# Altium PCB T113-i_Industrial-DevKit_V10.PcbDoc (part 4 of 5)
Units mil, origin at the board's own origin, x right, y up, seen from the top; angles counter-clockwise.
Board outline 4212.61 x 3188.98 mil, 4 copper layers (Top Layer, GND, PWR, Bottom Layer); 249 components, 236 nets, 911 pads, 571 vias.
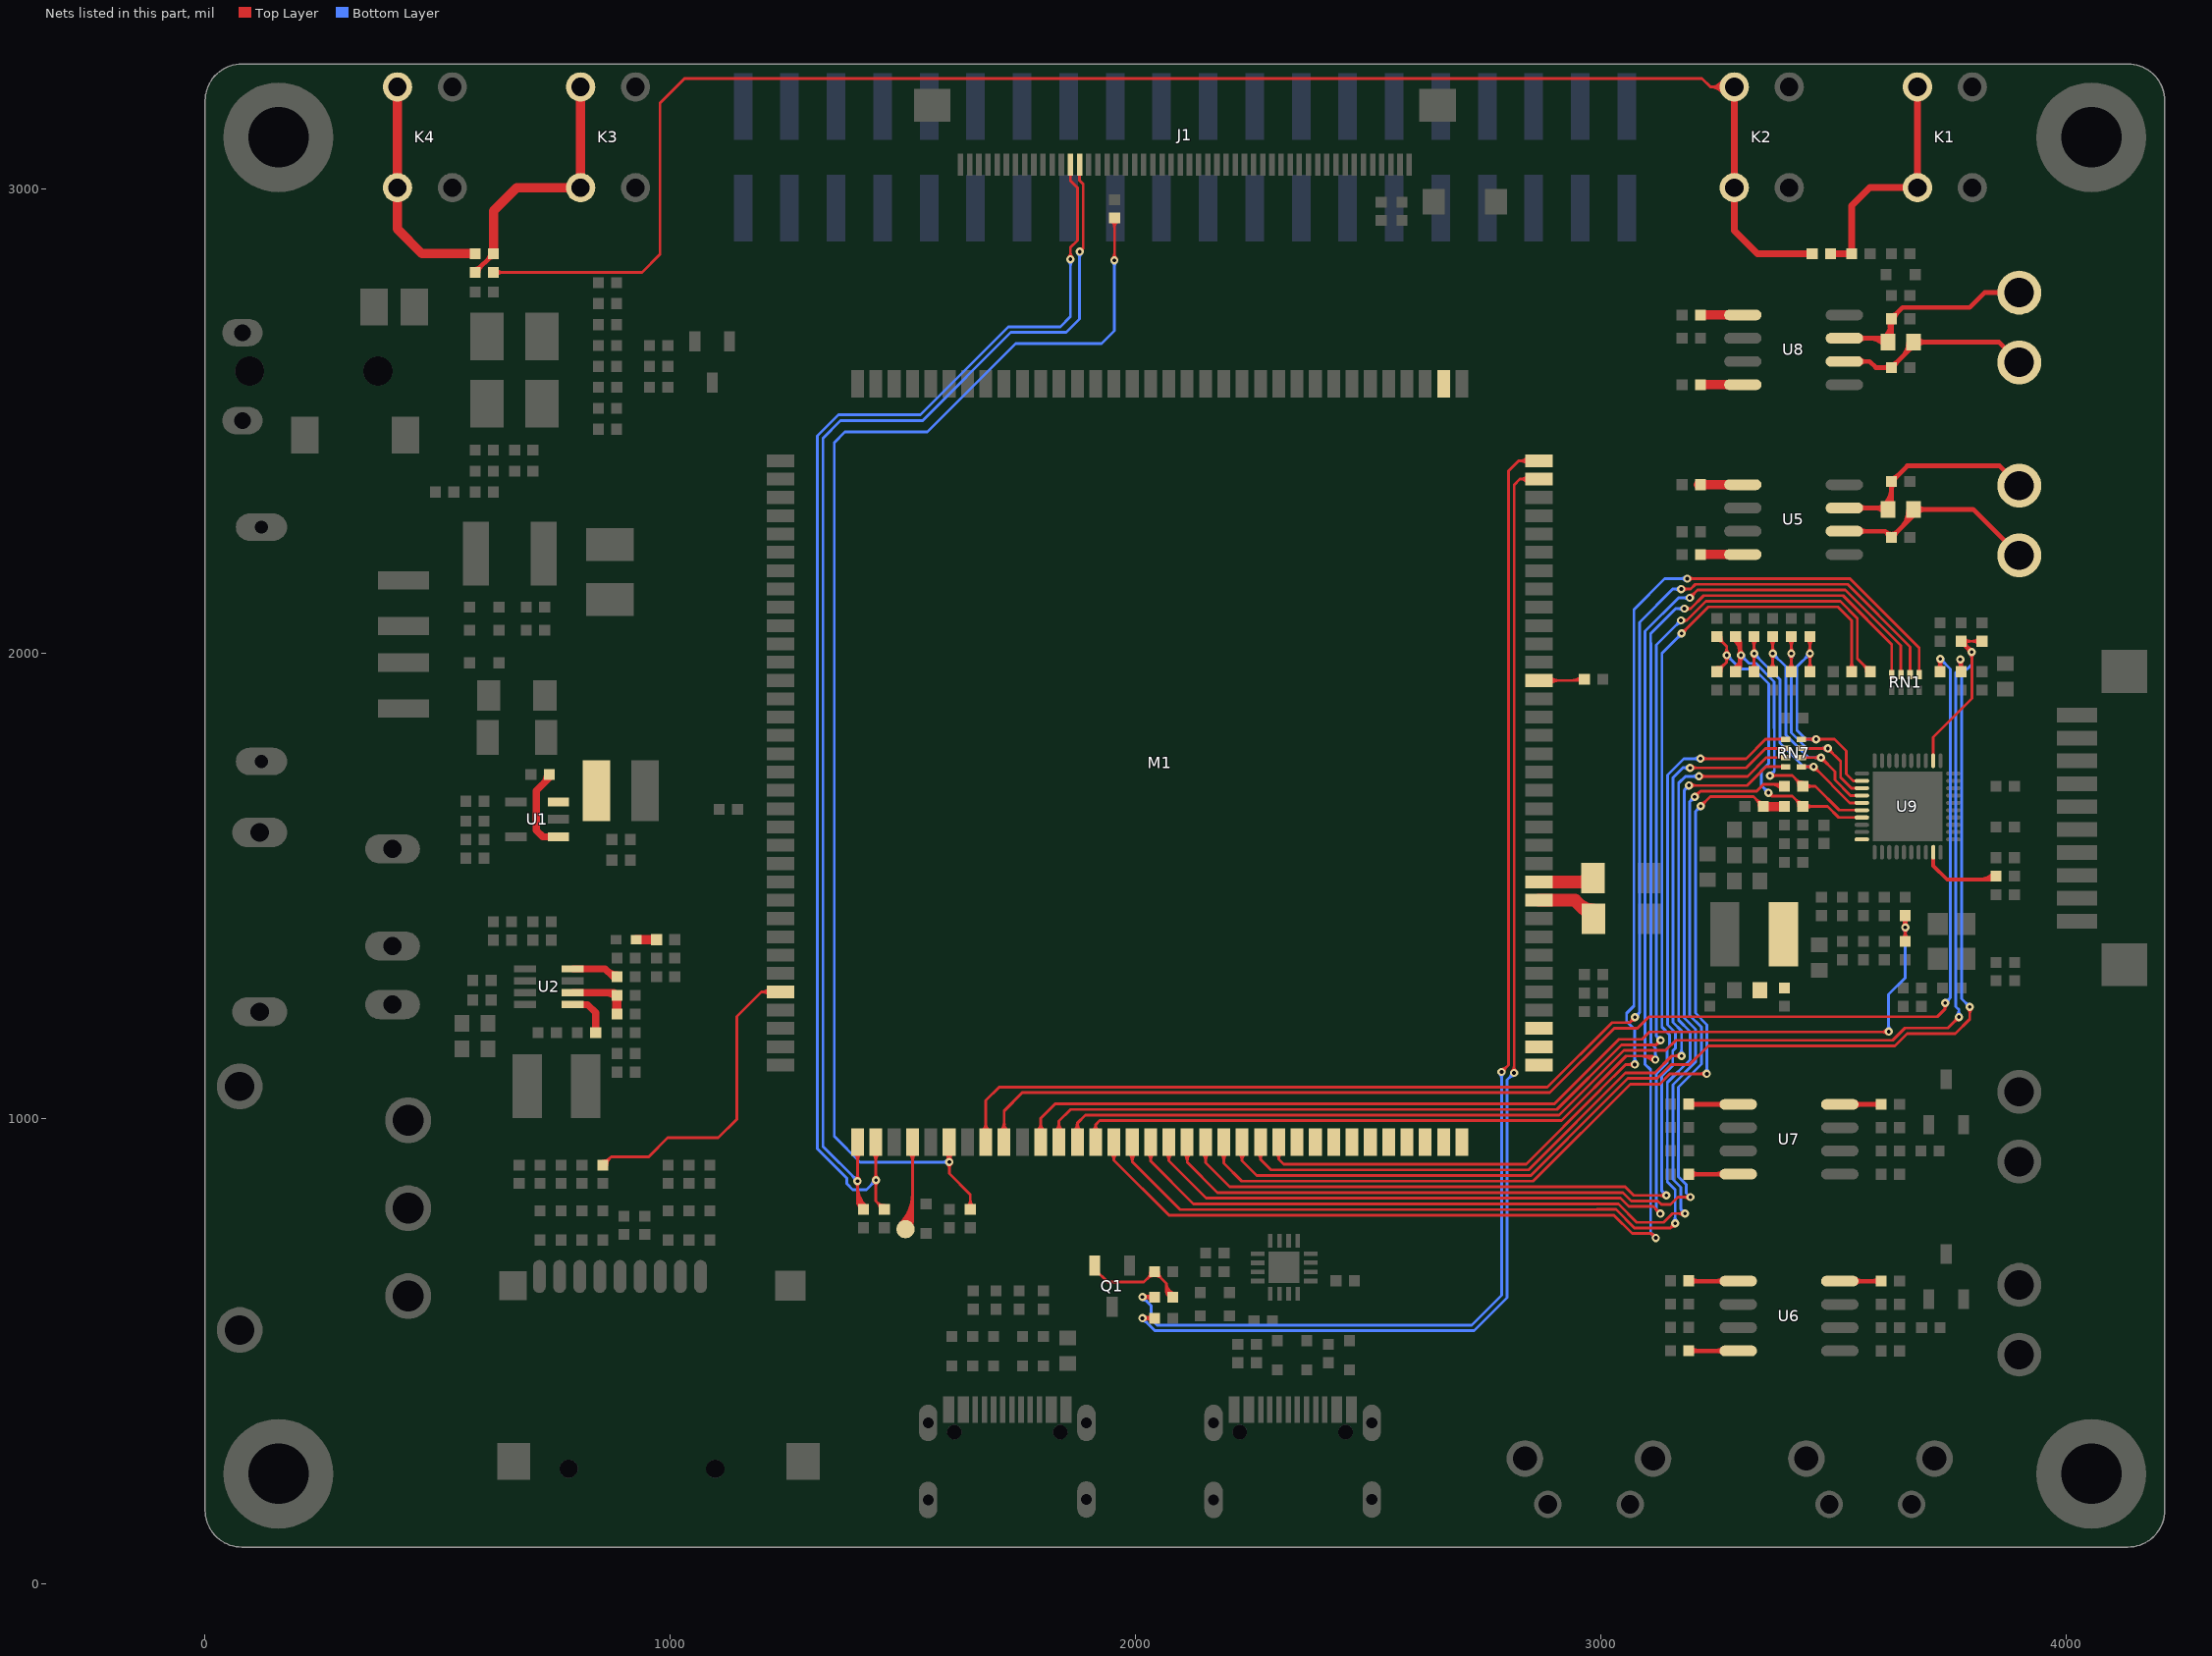
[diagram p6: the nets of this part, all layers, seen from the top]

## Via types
v1: diameter 17.72, hole 7.87, Top Layer to Bottom Layer, tented both sides, 571 vias

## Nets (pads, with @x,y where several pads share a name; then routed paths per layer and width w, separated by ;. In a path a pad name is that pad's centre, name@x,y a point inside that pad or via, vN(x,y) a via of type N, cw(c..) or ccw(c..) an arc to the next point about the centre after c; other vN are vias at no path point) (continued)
NetJ6_1: J6.1 R51.2 R52.1 U5.6 | length 634.6
  Top Layer w10: U5.6@3524.15,2263.15 3612.17,2263.15 R51.2@3625.31,2250 3672.56,2297.24 R52.1@3672.56,2310 3801.25,2310 J6.1@3900,2211.25 ; U5.6@3557.48,2258.5 cw(c3568.71,2247.28) 3568.71,2263.15 cw(c3568.71,2279.02) U5.6@3557.48,2267.8 ; R51.2@3618.5,2250 ccw(c3602.06,2250) 3613.69,2261.63 ccw(c3625.31,2273.25) 3625.31,2256.81 ccw(c3625.31,2273.25) 3636.94,2261.63 ccw(c3648.57,2250) R51.2@3632.13,2250 ; 3646.58,2271.27 ccw(c3609.82,2308.03) R52.1@3661.81,2308.03 ; 3663.65,2288.34 ccw(c3643.96,2308.03) R52.1@3671.81,2308.03 ; R52.1@3680.16,2302.4 cw(c3698.51,2284.05) 3698.51,2310 cw(c3698.51,2335.95) R52.1@3680.16,2317.6
NetJ6_2: J6.2 R52.2 R53.1 U5.7 | length 645.5
  Top Layer w10: U5.7@3524.15,2313.15 3614.29,2313.15 R52.2@3617.44,2310 3625.32,2317.87 R53.1@3625.32,2370 3659.12,2403.8 3857.45,2403.8 J6.2@3900,2361.26 ; U5.7@3557.48,2308.5 cw(c3568.71,2297.28) 3568.71,2313.15 cw(c3568.71,2329.02) U5.7@3557.48,2317.8 ; 3588.64,2313.15 cw(c3588.64,2283.17) R52.2@3609.84,2304.37 ; 3594.34,2313.15 ccw(c3594.34,2335.06) 3609.84,2319.57 ccw(c3572.48,2356.93) 3625.32,2356.93 ; R52.2@3616.91,2312.5 ccw(c3596.63,2332.78) 3625.32,2332.78 ; R53.1@3620.5,2365.18 cw(c3608.87,2353.56) 3625.32,2353.56 cw(c3641.76,2353.56) R53.1@3630.13,2365.18 ; R53.1@3625.32,2376.81 ccw(c3625.32,2393.25) 3636.94,2381.63 ccw(c3648.57,2370) R53.1@3632.13,2370
NetJ9_1: J9.1 R60.2 R61.1 U8.6 | length 584.8
  Top Layer w10: U8.6@3524.15,2628.15 3578.5,2628.15 3591.65,2615 R60.2@3625.31,2615 3672.56,2662.24 R61.1@3672.56,2670 3856.25,2670 J9.1@3900,2626.25 ; U8.6@3557.48,2623.5 cw(c3568.71,2612.28) 3568.71,2628.15 cw(c3568.71,2644.02) U8.6@3557.48,2632.8 ; R60.2@3620.5,2610.18 ccw(c3608.87,2598.56) 3608.87,2615 ccw(c3608.87,2631.44) R60.2@3620.5,2619.82 ; R60.2@3625.31,2621.81 ccw(c3625.31,2638.25) 3636.94,2626.63 ccw(c3648.57,2615) R60.2@3632.13,2615 ; 3650.12,2639.8 ccw(c3621.89,2668.03) R61.1@3661.81,2668.03 ; R61.1@3664.09,2653.78 cw(c3672.56,2645.31) R61.1@3672.56,2657.28 ; R61.1@3680.16,2662.4 cw(c3698.51,2644.05) 3698.51,2670 cw(c3698.51,2695.95) R61.1@3680.16,2677.6
NetJ9_2: J9.2 R61.2 R62.1 U8.7 | length 669.3
  Top Layer w10: U8.7@3524.15,2678.15 3609.29,2678.15 R61.2@3617.44,2670 3625.32,2677.87 R62.1@3625.32,2720 3649.45,2744.14 3793.19,2744.14 3825.31,2776.26 J9.2@3900,2776.26 ; U8.7@3557.48,2673.5 cw(c3568.71,2662.28) 3568.71,2678.15 cw(c3568.71,2694.02) U8.7@3557.48,2682.8 ; 3576.57,2678.15 cw(c3576.57,2631.1) R61.2@3609.84,2664.37 ; 3600.71,2678.15 cw(c3600.71,2655.24) R61.2@3616.91,2671.44 ; R61.2@3609.84,2679.57 ccw(c3572.48,2716.93) R62.1@3625.32,2716.93 ; R61.2@3616.91,2672.5 ccw(c3596.63,2692.78) 3625.32,2692.78 ; R62.1@3619.42,2716.59 cw(c3602.82,2707.01) 3621.33,2702.06 ; R62.1@3620.5,2715.18 cw(c3608.87,2703.56) 3625.32,2703.56 cw(c3641.76,2703.56) R62.1@3630.13,2715.18 ; 3622.32,2705.77 cw(c3635.58,2702.21) R62.1@3628.72,2714.1 ; R62.1@3625.32,2726.81 ccw(c3625.32,2743.25) 3636.94,2731.63 ccw(c3648.57,2720) R62.1@3632.13,2720
NetK1_1: K1.1 K1.2 R14.1 R16.2 | length 522.4
  Top Layer w15: R16.2@3494.37,2860 R14.1@3540,2860 3540,2963 3578.96,3001.96 K1.1@3681.1,3001.96 K1.2@3681.1,3218.51
NetK2_1: K2.1 K2.2 R16.1 R19.2 | length 3684.1
  Top Layer w6: R19.2@619.69,2820 939.38,2820 977.79,2858.41 977.79,3183.72 1030.71,3236.64 3218.09,3236.64 3236.23,3218.51 ; R19.2@625.92,2813.77 cw(c640.96,2798.73) 640.96,2820 cw(c640.96,2841.27) R19.2@625.92,2826.23 ; K2.2@3263.18,3203.5 ccw(c3236.23,3186.81) 3236.23,3218.51 ; K2.2@3263.18,3233.52 cw(c3236.23,3250.21) 3236.23,3218.51 ; K2.2@3268.28,3206.66 ccw(c3247,3193.48) 3247,3218.51 ccw(c3247,3243.54) K2.2@3268.28,3230.36 ; K2.2@3287.4,3218.51 3236.23,3218.51
  Top Layer w15: K2.2@3287.4,3218.51 K2.1@3287.4,3001.96 3287.4,2909.6 3337,2860 R16.1@3455,2860
NetK3_1: K3.1 K3.2 R19.1 R23.2 | length 624.4
  Top Layer w10: R19.1@580.32,2820 619.69,2859.37 R23.2@619.69,2860 ; R19.1@580.32,2826.81 ccw(c580.32,2843.25) 591.94,2831.63 ccw(c603.57,2820) R19.1@587.13,2820 ; 607.61,2847.3 ccw(c594.91,2860) R23.2@612.87,2860 ; R23.2@609.13,2848.82 cw(c619.69,2838.27) R23.2@619.69,2853.19
  Top Layer w20: R23.2@619.69,2860 619.69,2951.69 669.96,3001.96 K3.1@807.09,3001.96 K3.2@807.09,3218.51
NetK4_1: K4.1 K4.2 R23.1 | length 494.6
  Top Layer w20: K4.2@413.39,3218.51 K4.1@413.39,3001.96 413.39,2912.67 466.05,2860 R23.1@580.32,2860
NetL1_1: L1.1 U1.3
NetLED1_1: LED1.1 R12.1 | length 43.7
  Top Layer w20: LED1.1@926.65,1385 R12.1@970.32,1385
NetM1_38: M1.38 TP1.1 | length 495.2
  Top Layer w6: TP1.1@1493.8,774.17 ccw(c1428.93,839.04) 1520.67,839.04 ; TP1.1@1498.04,769.93 ccw(c1443.42,824.55) 1520.67,824.55 ; TP1.1@1502.29,765.69 ccw(c1457.9,810.07) 1520.67,810.07 ; TP1.1@1505.6,762.37 1520.67,777.44 ; TP1.1@1506.53,761.44 ccw(c1472.39,795.58) 1520.67,795.58 ; TP1.1@1510.77,757.2 ccw(c1486.87,781.1) 1520.67,781.1 ; M1.38@1513.05,926.63 cw(c1494.64,908.23) 1520.67,908.23 cw(c1546.69,908.23) M1.38@1528.29,926.63 ; TP1.1@1514.22,776.66 ccw(c1516.94,781.17) 1520.67,777.44 ; TP1.1@1519.88,771 cw(c1524.39,773.72) 1520.67,777.44 ; M1.38@1520.67,950 1520.67,777.44
NetM1_78: M1.78 R65.1 | length 169.1
  Top Layer w28: M1.78@2867.13,1469.69 2945.08,1469.69 R65.1@2984.76,1430 ; 2953.22,1461.55 ccw(c2984.76,1493.1) R65.1@2984.76,1448.48
NetM1_79: M1.79 R66.1 | length 142.6
  Top Layer w28: M1.79@2867.13,1509.06 2975.64,1509.06 R66.1@2983.77,1517.19 ; 2955.65,1509.06 ccw(c2955.65,1537.83) R66.1@2975.99,1517.48
NetM1_90: M1.90 R67.2 | length 186.7
  Top Layer w6: M1.90@2867.13,1942.13 2962.44,1942.13 R67.2@2965.31,1945 ; M1.90@2890.5,1934.5 cw(c2908.9,1916.1) 2908.9,1942.13 cw(c2908.9,1968.15) M1.90@2890.5,1949.75 ; 2937.11,1942.13 ccw(c2937.11,1973.21) R67.2@2959.08,1951.23 ; 2950.98,1942.13 cw(c2950.98,1930.67) R67.2@2959.08,1938.77 ; 2951.59,1942.13 ccw(c2951.59,1958.72) R67.2@2963.33,1946.99
NetQ1_2: Q1.2 R35.2 R37.2 | length 401.9
  Top Layer w6: Q1.2@1912.6,684.29 1912.6,676.1 1940.28,648.41 2018.18,648.41 R37.2@2040.98,671.22 2066.53,645.68 ; R37.2@2032.17,671.22 cw(c2010.9,671.22) 2025.94,656.18 cw(c2040.98,641.14) 2040.98,662.41 cw(c2040.98,641.14) 2056.03,656.18 cw(c2071.07,671.22) R37.2@2049.8,671.22 ; 2066.53,637.87 ccw(c2086.12,637.87) R35.2@2081.08,618.94 ; R35.2@2071.56,616.76 ccw(c2054.3,617.82) 2066.53,630.05 ; R35.2@2079.53,613.14 cw(c2084.04,630.06) 2066.53,630.06 ; R35.2@2079.81,625.01 cw(c2078.76,642.28) 2066.53,630.05 ; R35.2@2080.35,616.22 2066.53,630.05 ; R35.2@2082.62,624.73 cw(c2088.2,645.68) 2066.53,645.68 ; 2066.53,630.05 2066.53,645.68
NetR1_1: R1.1 U1.1 | length 206.4
  Top Layer w15: 727.09,1720 ccw(c707.08,1740) R1.1@735.37,1740 ; R1.1@739.68,1740 739.68,1732.59 712,1704.91 712,1620 725.65,1606.35 U1.1@759.08,1606.35
NetR4_1: R4.1 R7.2 U2.6 | length 161.6
  Top Layer w15: U2.6@790.26,1270.92 879.39,1270.92 R4.1@885.32,1265 ; 860.61,1270.92 cw(c860.61,1240.3) R4.1@882.27,1261.95
  Top Layer w20: R7.2@885.31,1225 R4.1@885.32,1265
NetR8_2: R8.2 U2.8 | length 126.3
  Top Layer w15: U2.8@790.26,1322.1 859.8,1322.1 876.91,1305 R8.2@885.31,1305 ; 863.6,1318.3 ccw(c885.31,1340.02) R8.2@885.31,1309.31
NetR9_2: R9.2 U2.5 | length 99.5
  Top Layer w15: U2.5@790.26,1245.33 822.21,1245.33 839.69,1227.85 R9.2@839.69,1185
NetR43_2: R43.2 U5.4 | length 91.2
  Top Layer w20: R43.2@3214.69,2213.15 U5.4@3305.85,2213.15
NetR44_2: R44.2 U5.1 | length 95.6
  Top Layer w20: R44.2@3210.24,2363.15 U5.1@3305.85,2363.15
NetR45_1: R45.1 U6.4 | length 157.2
  Top Layer w10: R45.1@3189.68,501.26 3190.31,500.63 U6.4@3295.85,500.63 ; R45.1@3194.5,496.44 cw(c3204.61,486.34) 3204.61,500.63 ; R45.1@3194.5,506.08 ccw(c3207.65,519.22) 3207.65,500.63 ; U6.4@3262.52,495.98 ccw(c3251.29,484.76) 3251.29,500.63 ccw(c3251.29,516.5) U6.4@3262.52,505.28
NetR46_1: R46.1 U6.1 | length 157.2
  Top Layer w10: R46.1@3189.68,651.26 3190.31,650.63 U6.1@3295.85,650.63 ; R46.1@3194.5,646.44 cw(c3204.61,636.34) 3204.61,650.63 ; R46.1@3194.5,656.08 ccw(c3207.65,669.22) 3207.65,650.63 ; U6.1@3262.52,645.98 ccw(c3251.29,634.76) 3251.29,650.63 ccw(c3251.29,666.5) U6.1@3262.52,655.28
NetR47_1: R47.1 U7.4 | length 156.9
  Top Layer w10: R47.1@3189.68,880.63 U7.4@3295.85,880.63 ; R47.1@3194.5,875.81 cw(c3206.13,864.19) 3206.13,880.63 cw(c3206.13,897.07) R47.1@3194.5,885.45 ; U7.4@3262.52,875.98 ccw(c3251.29,864.76) 3251.29,880.63 ccw(c3251.29,896.5) U7.4@3262.52,885.28
NetR48_1: R48.1 U7.1 | length 157.2
  Top Layer w10: R48.1@3189.68,1031.26 3190.31,1030.63 U7.1@3295.85,1030.63 ; R48.1@3194.5,1026.44 cw(c3204.61,1016.34) 3204.61,1030.63 ; R48.1@3194.5,1036.08 ccw(c3207.65,1049.22) 3207.65,1030.63 ; U7.1@3262.52,1025.98 ccw(c3251.29,1014.76) 3251.29,1030.63 ccw(c3251.29,1046.5) U7.1@3262.52,1035.28
NetR49_2: R49.2 U6.8 | length 140
  Top Layer w10: U6.8@3514.15,650.63 R49.2@3603.39,650.63 ; U6.8@3547.48,645.98 cw(c3558.71,634.76) 3558.71,650.63 cw(c3558.71,666.5) U6.8@3547.48,655.28 ; R49.2@3598.57,645.81 ccw(c3586.94,634.19) 3586.94,650.63 ccw(c3586.94,667.07) R49.2@3598.57,655.45
NetR50_2: R50.2 U7.8 | length 140
  Top Layer w10: U7.8@3514.15,1030.63 R50.2@3603.39,1030.63 ; U7.8@3547.48,1025.98 cw(c3558.71,1014.76) 3558.71,1030.63 cw(c3558.71,1046.5) U7.8@3547.48,1035.28 ; R50.2@3598.57,1025.81 ccw(c3586.94,1014.19) 3586.94,1030.63 ccw(c3586.94,1047.07) R50.2@3598.57,1035.45
NetR58_2: R58.2 U8.4 | length 90.6
  Top Layer w20: R58.2@3215.24,2578.15 U8.4@3305.85,2578.15
NetR59_2: R59.2 U8.1 | length 90.6
  Top Layer w20: R59.2@3215.24,2728.15 U8.1@3305.85,2728.15
PB8: M1.101 R36.1 | length 2859
  Top Layer w6: v1(2014.89,570.92) 2040.9,570.92 R36.1@2040.98,571 ; v1@2018.66,575.4 ccw(c2025.53,583.59) 2028.29,573.27 ; v1@2018.74,566.49 cw(c2025.55,558.66) 2028.23,568.69 ; v1@2019.04,566.77 cw(c2029.04,556.77) 2029.04,570.92 cw(c2029.04,585.06) v1@2019.04,575.06 ; v1@2019.51,570.92 ccw(c2019.51,592.47) R36.1@2034.75,577.23 ; v1@2019.92,570.92 cw(c2019.92,549.93) R36.1@2034.75,564.77 ; v1@2019.97,567.99 cw(c2028.68,562.95) 2026.08,572.68 ; v1@2019.97,573.85 ccw(c2028.37,578.7) 2025.86,569.32 ; v1@2809.71,1102.43 ccw(c2798.89,1113.26) 2814.2,1113.26 ; v1@2814.2,1098.29 2814.2,2362.88 2826.52,2375.2 ; 2814.2,1111.6 ccw(c2827.17,1111.6) v1@2818,1102.43 ; M1.101@2843.51,2367.83 ccw(c2826.52,2351.92) 2826.52,2375.2 ; M1.101@2843.51,2382.57 cw(c2826.52,2398.48) 2826.52,2375.2 ; M1.101@2867.13,2375.2 2826.52,2375.2
  Bottom Layer w6: v1@2014.89,565.06 cw(c2014.89,550.91) 2024.9,560.92 cw(c2034.9,570.92) v1@2020.75,570.92 ; v1(2014.89,570.92) 2041.7,544.11 2728.06,544.11 2799.1,615.15 2799.1,1083.53 v1(2813.86,1098.29) ; v1@2808,1098.29 cw(c2793.86,1098.29) 2803.86,1088.29 cw(c2813.86,1078.29) v1@2813.86,1092.43
PB9: M1.102 R35.1 | length 2918.8
  Top Layer w6: v1(2014.89,616.5) 2040.7,616.5 R35.1@2040.98,616.22 ; v1@2018.57,611.94 cw(c2025.5,603.32) 2028.36,614 ; v1@2018.83,620.84 ccw(c2025.57,628.28) 2028.17,618.59 ; v1@2019.04,612.36 cw(c2029.04,602.36) 2029.04,616.5 cw(c2029.04,630.65) v1@2019.04,620.65 ; v1@2019.03,616.51 cw(c2019.03,594.26) R35.1@2034.75,609.99 ; v1@2019.97,613.58 cw(c2028,608.94) 2025.6,617.9 ; v1@2019.97,619.43 ccw(c2029.05,624.68) 2026.34,614.55 ; v1@2020.4,616.5 ccw(c2020.4,636.8) R35.1@2034.75,622.45 ; v1(2787.05,1100.58) 2801.83,1115.36 2801.83,2392.66 2823.73,2414.57 M1.102@2867.13,2414.57 ; v1@2787.05,1106.44 ccw(c2787.05,1120.58) 2797.05,1110.58 ccw(c2807.05,1100.58) v1@2792.91,1100.58 ; M1.102@2843.76,2406.95 ccw(c2825.35,2388.54) 2825.35,2414.57 ccw(c2825.35,2440.59) M1.102@2843.76,2422.19
  Bottom Layer w6: v1@2014.89,610.65 cw(c2014.89,596.5) 2024.89,606.5 cw(c2034.9,616.5) v1@2020.75,616.5 ; v1(2014.89,616.5) 2033.91,597.49 2033.91,568.87 2046.67,556.11 2723.09,556.11 2787.1,620.12 2787.1,1100.53 v1(2787.05,1100.58) ; v1@2782.91,1096.44 cw(c2772.79,1086.32) 2787.1,1086.32 ; 2787.1,1086.55 cw(c2801.08,1086.55) v1@2791.2,1096.44
PB12: M1.104
PG6: M1.68
PG7: M1.67
PG8: M1.66
PG9: M1.65
PG10: M1.64
PG11: M1.63
PG12: M1.59
PG13: M1.60
PG14: M1.61
PG15: M1.62
PG16: M1.71
PG17: M1.69
PG18: M1.70
PHYRSTB: C70.1 M1.56 R84.1 U9.12 | length 3214.8
  Top Layer w6: M1.56@2221.96,926.39 cw(c2205.99,909.36) 2229.33,909.36 ; M1.56@2229.33,950 2229.33,909.36 ; M1.56@2236.71,926.39 ccw(c2252.67,909.36) 2229.33,909.36 ; 3009.99,1038.05 3058.34,1086.4 3121.67,1086.4 3151.43,1116.16 3191.06,1116.16 3231.29,1156.39 3632.79,1156.39 3659.26,1182.85 3762.56,1182.85 3793.68,1213.97 v1(3793.68,1240.2) ; 3010.15,1037.88 2850.03,877.76 2260.93,877.76 2229.33,909.36 ; U9.12@3715.1,1769.66 3715.1,1820.37 3798.03,1903.3 v1(3798.03,2003.54) C70.1@3775,2026.57 R84.1@3820,2026.57 ; C70.1@3775,2017.76 cw(c3775,1996.49) 3790.04,2011.53 cw(c3805.08,2026.57) C70.1@3783.81,2026.57 ; C70.1@3781.13,2016.68 cw(c3769.07,1995.78) v1@3792.37,2002.03 ; C70.1@3781.23,2020.34 cw(c3796.27,2005.3) 3796.27,2026.57 cw(c3796.27,2047.85) C70.1@3781.23,2032.81 ; C70.1@3784.9,2020.44 ccw(c3805.79,2032.51) v1@3799.55,2009.2 ; 3788.58,2012.38 cw(c3784.79,2005.82) v1@3792.26,2004.54 ; 3789.2,2013 ccw(c3795.76,2016.78) v1@3797.04,2009.32 ; v1@3789.54,1236.06 cw(c3779.54,1226.06) 3793.68,1226.06 cw(c3807.82,1226.06) v1@3797.82,1236.06 ; v1@3792.17,2003.54 ccw(c3778.03,2003.54) 3788.03,2013.55 ccw(c3798.03,2023.55) v1@3798.03,2009.4 ; v1@3793.89,1999.4 cw(c3783.89,1989.4) 3798.03,1989.4 cw(c3812.17,1989.4) v1@3802.17,1999.4 ; R84.1@3813.77,2020.34 ccw(c3798.73,2005.3) 3798.73,2026.57 ccw(c3798.73,2047.85) R84.1@3813.77,2032.81
  Bottom Layer w6: v1@3787.82,1240.2 ccw(c3773.68,1240.2) 3783.68,1250.2 ccw(c3793.68,1260.2) v1@3793.68,1246.06 ; v1(3793.68,1240.2) 3776.28,1257.6 3776.28,1955.19 3798.03,1976.95 v1(3798.03,2003.54) ; v1@3793.89,1999.4 cw(c3783.89,1989.4) 3798.03,1989.4 cw(c3812.17,1989.4) v1@3802.17,1999.4
REGOUT: C69.1 L3.1 R88.2 U9.30
RESET: M1.40 R69.2 R70.1 | length 3132
  Top Layer w6: M1.40@1591.79,926.63 cw(c1572.49,907.34) v1@1599.78,907.34 ; v1@1594.72,909.49 ccw(c1582.12,916.85) M1.40@1596.22,920.63 ; v1@1595.64,902.39 cw(c1585.64,892.39) 1599.78,892.39 cw(c1613.92,892.39) v1@1603.92,902.39 ; v1@1595.64,910.68 ccw(c1585.64,920.68) 1599.78,920.68 ccw(c1613.92,920.68) v1@1603.92,910.68 ; 1596.45,919.77 ccw(c1609.42,923.25) v1@1602.71,911.61 ; v1@1596.85,911.61 ccw(c1590.92,921.88) 1602.38,918.81 ; M1.40@1599.41,950 1599.78,949.63 v1(1599.78,906.54) 1599.78,881.94 1645,836.72 R69.2@1645,804.69 ; v1@1599.78,909.12 cw(c1624.54,909.12) M1.40@1607.03,926.63 ; 1602.8,920.38 ccw(c1615.12,917.08) v1@1604.61,909.86 ; R69.2@1638.77,810.92 ccw(c1623.73,825.96) 1645,825.96 ccw(c1666.27,825.96) R69.2@1651.23,810.92 ; R70.1@1948.77,2930.34 cw(c1933.73,2915.3) 1955,2915.3 cw(c1976.27,2915.3) R70.1@1961.23,2930.34 ; v1@1950.49,2849.83 ccw(c1939.6,2860.72) 1955,2860.72 ; v1(1954.63,2845.69) 1955,2846.05 R70.1@1955,2936.57 ; 1955,2858.94 ccw(c1967.89,2858.94) v1@1958.78,2849.83
  Bottom Layer w6: v1@1595.64,902.39 ccw(c1585.64,892.39) 1585.64,906.54 ccw(c1585.64,920.68) v1@1595.64,910.68 ; v1(1599.78,906.54) 1407.8,906.54 1352.35,961.99 1352.35,2453.56 1375.41,2476.62 1552.2,2476.62 1742.25,2666.67 1927.39,2666.67 1954.63,2693.91 v1(1954.63,2845.69) ; v1@1950.49,2841.54 cw(c1940.49,2831.54) 1954.63,2831.54 cw(c1968.78,2831.54) v1@1958.78,2841.54
RGMII_CLKIN_125M: C61.1 M1.45 R68.2 | length 2495.3
  Top Layer w6: M1.45@1788.64,973.37 ccw(c1770.24,991.77) 1796.26,991.77 ccw(c1822.28,991.77) M1.45@1803.88,973.37 ; M1.45@1796.26,954.42 1796.26,1000.61 1827.38,1031.74 2900.59,1031.74 3039.51,1170.66 3089.22,1170.66 3104.99,1186.43 v1@3619.23,1186.43 ; 3603.29,1186.43 ccw(c3603.29,1203.12) v1@3615.09,1191.32 ; 3606.89,1186.43 cw(c3606.89,1174.84) v1@3615.09,1183.03 ; C61.1@3648.77,1387.18 ccw(c3633.73,1402.22) 3655,1402.22 ccw(c3676.27,1402.22) C61.1@3661.23,1387.18 ; R68.2@3648.77,1430.34 cw(c3633.73,1415.3) 3655,1415.3 cw(c3676.27,1415.3) R68.2@3661.23,1430.34 ; v1@3650.55,1414.92 ccw(c3642.86,1421.5) 3652.64,1424.12 ; v1@3650.86,1406.97 cw(c3640.86,1396.97) 3655,1396.97 cw(c3669.14,1396.97) v1@3659.14,1406.97 ; v1@3650.86,1415.25 ccw(c3640.86,1425.25) 3655,1425.25 ccw(c3669.14,1425.25) v1@3659.14,1415.25 ; v1@3652.07,1416.18 ccw(c3646.85,1425.22) 3656.93,1422.52 ; 3653.07,1422.52 ccw(c3663.15,1425.22) v1@3657.93,1416.18 ; C61.1@3655,1380.94 v1(3655,1411.11) R68.2@3655,1436.57 ; 3657.36,1424.12 ccw(c3667.14,1421.5) v1@3659.45,1414.92
  Bottom Layer w6: v1@3615.09,1191.32 ccw(c3605.09,1201.32) 3619.23,1201.32 ccw(c3633.38,1201.32) v1@3623.38,1191.32 ; v1(3619.23,1187.18) 3619.23,1266.9 3655,1302.67 v1(3655,1411.11) ; v1@3650.86,1406.97 cw(c3640.86,1396.97) 3655,1396.97 cw(c3669.14,1396.97) v1@3659.14,1406.97
RGMII_MDC: M1.47 R76.2 | length 3014.7
  Top Layer w6: M1.47@1867.72,973.7 ccw(c1852.57,990.24) 1875,990.24 ; M1.47@1875,950 1875,990.24 ; M1.47@1882.28,973.7 cw(c1897.43,990.24) 1875,990.24 ; v1@3764.46,1218.45 cw(c3750.32,1218.45) 3760.32,1208.45 cw(c3770.32,1198.45) v1@3770.32,1212.59 ; R76.2@3768.77,1967.18 ccw(c3758.18,1977.77) 3773.16,1977.77 ; v1@3769.01,1983.26 cw(c3759.01,1973.26) 3773.16,1973.26 cw(c3787.3,1973.26) v1@3777.3,1983.26 ; v1@3770.23,1982.33 cw(c3763.48,1970.65) 3776.51,1974.14 ; v1(3770.32,1218.45) 3746.72,1194.85 3654.28,1194.85 3627.82,1168.39 3161.62,1168.39 3139.89,1146.66 3049.95,1146.66 2911.03,1007.74 1892.5,1007.74 1875,990.24 ; v1@3773.16,1986.67 ccw(c3800.72,1986.67) R76.2@3781.23,1967.18 ; v1(3773.16,1987.41) 3773.16,1962.79 R76.2@3775,1960.94 ; v1@3774.9,1989.35 v1@3775,1989.25 ; 3776.75,1973.25 cw(c3791.04,1977.08) v1@3778.23,1984.48
  Bottom Layer w6: v1@3766.18,1222.59 ccw(c3756.18,1232.59) 3770.32,1232.59 ccw(c3784.46,1232.59) v1@3774.46,1222.59 ; v1@3769.01,1983.26 cw(c3759.01,1973.26) 3773.16,1973.26 cw(c3787.3,1973.26) v1@3777.3,1983.26 ; v1(3770.32,1218.45) 3770.32,1234.31 3763.82,1240.81 3763.82,1959.71 3773.16,1969.04 v1(3773.16,1987.41)
RGMII_MDIO: M1.43 R75.2 | length 3169.8
  Top Layer w6: M1.43@1709.9,973.37 ccw(c1691.5,991.77) 1717.52,991.77 ccw(c1743.54,991.77) M1.43@1725.14,973.37 ; M1.43@1717.52,950 1717.52,1016.72 1756.59,1055.79 2890.62,1055.79 3029.49,1194.66 3079.18,1194.66 3103.77,1219.25 3723.93,1219.25 3740.77,1236.09 ; R75.2@3723.77,1967.18 ccw(c3708.73,1982.22) 3730,1982.22 ccw(c3751.27,1982.22) R75.2@3736.23,1967.18 ; v1@3725.56,1984.98 cw(c3716.1,1977.33) 3727.85,1974.18 ; v1@3725.97,1984.52 cw(c3716.25,1974.79) 3730,1974.79 ; v1@3727.19,1983.58 cw(c3723.15,1976.59) 3730.95,1978.68 ; 3728.93,1978.22 cw(c3737.46,1975.94) v1@3733.04,1983.58 ; R75.2@3730,1960.94 3730,1988.54 v1(3730.12,1988.66) ; 3730,1974.24 cw(c3744.54,1974.24) v1@3734.26,1984.52 ; 3732.05,1974.56 cw(c3742.7,1977.41) v1@3734.48,1984.75 ; v1@3736.99,1244.21 cw(c3730.15,1236.09) 3740.77,1236.09 ; v1(3740.77,1248.69) 3740.77,1236.09 ; v1@3744.54,1244.21 ccw(c3751.39,1236.09) 3740.77,1236.09
  Bottom Layer w6: v1@3730.12,1982.8 cw(c3730.12,1968.66) 3740.12,1978.66 cw(c3750.12,1988.66) v1@3735.97,1988.66 ; v1(3730.12,1988.66) 3751.82,1966.95 3751.82,1259.74 v1(3740.77,1248.69) ; v1@3740.77,1254.55 ccw(c3740.77,1268.69) 3750.77,1258.69 ccw(c3760.77,1248.69) v1@3746.63,1248.69
RGMII_RXCK: C62.1 M1.55 R71.2 | length 2146.8
  Top Layer w6: M1.55@2182.34,926.63 cw(c2163.94,908.23) 2189.96,908.23 cw(c2215.98,908.23) M1.55@2197.58,926.63 ; M1.55@2189.96,950 2189.96,904.17 2228.46,865.67 2855.01,865.67 3063.74,1074.4 3126.85,1074.4 3148.91,1096.45 v1(3228.29,1096.45) ; v1(3215.34,1672.17) 3235.61,1692.43 3328.51,1692.43 C62.1@3349.68,1671.26 ; v1@3215.34,1678.02 ccw(c3215.34,1692.17) 3225.34,1682.17 ccw(c3235.34,1672.17) v1@3221.2,1672.17 ; v1@3224.14,1092.31 ccw(c3214.14,1082.31) 3214.14,1096.45 ccw(c3214.14,1110.6) v1@3224.14,1100.6 ; C62.1@3340.87,1671.26 ccw(c3319.6,1671.26) 3334.64,1686.3 ccw(c3349.68,1701.34) C62.1@3349.68,1680.07
  Top Layer w20: C62.1@3349.68,1671.26 R71.2@3395.31,1671.26
  Bottom Layer w6: v1@3209.48,1672.17 cw(c3195.34,1672.17) 3205.34,1662.17 cw(c3215.34,1652.16) v1@3215.34,1666.31 ; v1(3215.34,1672.17) 3203.81,1660.63 3203.81,1226.77 3228.51,1202.07 3228.51,1158.8 ; v1@3224.14,1100.6 ccw(c3213.66,1111.09) 3228.49,1111.09 ; v1(3228.29,1096.45) 3228.49,1096.66 3228.49,1158.8 ; 3228.49,1110.11 ccw(c3241.94,1110.11) v1@3232.43,1100.6
RGMII_RXCTL: M1.53 R72.2 | length 2434.6
  Top Layer w6: M1.53@2103.6,926.63 cw(c2085.2,908.23) 2111.22,908.23 cw(c2137.24,908.23) M1.53@2118.84,926.63 ; M1.53@2111.22,950 2111.22,906.11 2176.19,841.14 3047.87,841.14 3066.06,822.94 3123.2,822.94 3130.98,815.17 3150.32,815.17 3166.42,831.27 v1(3193,831.27) ; v1@3188.85,827.13 ccw(c3178.85,817.13) 3178.85,831.27 ccw(c3178.85,845.41) v1@3188.85,835.41 ; v1(3202.23,1691.93) 3214.73,1704.43 3335.47,1704.43 3350.28,1719.24 3391.07,1719.24 R72.2@3395.31,1715 ; v1@3202.23,1697.79 ccw(c3202.23,1711.93) 3212.23,1701.93 ccw(c3222.23,1691.93) v1@3208.09,1691.93 ; 3363.79,1719.25 cw(c3363.79,1683.48) R72.2@3389.08,1708.77 ; 3378.28,1719.25 cw(c3378.28,1697.97) R72.2@3393.33,1713.01
  Bottom Layer w6: v1(3193,831.27) 3184.39,839.88 3184.39,858.23 3167.45,875.17 3167.45,1068 3216.49,1117.04 3216.49,1197.12 3191.81,1221.8 3191.81,1681.51 v1(3202.23,1691.93) ; v1@3196.37,1691.93 cw(c3182.23,1691.93) 3192.23,1681.93 cw(c3202.23,1671.93) v1@3202.23,1686.07
RGMII_RXD0: M1.51 RN7.5 | length 2579.2
  Top Layer w6: M1.51@2025.02,926.47 cw(c2008.27,908.99) 2032.48,908.99 ; M1.51@2032.48,950 2032.48,908.99 ; M1.51@2039.94,926.47 ccw(c2056.69,908.99) 2032.48,908.99 ; v1@3177.29,791.74 ccw(c3167.29,781.74) 3167.29,795.88 ccw(c3167.29,810.03) v1@3177.29,800.03 ; v1(3181.44,795.88) 3154.4,795.88 3135.56,777.04 3077.79,777.04 3038.12,816.72 2124.75,816.72 2032.48,908.99 ; v1(3190.03,1716.61) 3190.21,1716.43 3315.28,1716.43 3355.58,1756.73 RN7.5@3398.17,1756.73 ; v1@3194.17,1712.47 cw(c3203.74,1702.9) 3203.74,1716.43 ; v1@3194.17,1720.75 ccw(c3204.6,1731.18) 3204.6,1716.43 ; RN7.5@3392.08,1754.68 ccw(c3387.12,1749.72) 3387.12,1756.73 ccw(c3387.12,1763.75) RN7.5@3392.08,1758.79
  Bottom Layer w6: v1@3175.59,796.31 ccw(c3164.57,797.12) 3172.39,804.93 ; v1@3181.01,801.73 cw(c3180.2,812.75) 3172.39,804.93 ; v1(3181.44,795.88) 3172.39,804.93 ; v1@3184.17,1716.61 cw(c3170.03,1716.61) 3180.03,1706.61 cw(c3190.03,1696.61) v1@3190.03,1710.75 ; v1(3190.03,1716.61) 3179.81,1706.39 3179.81,1216.83 3204.35,1192.29 3204.35,1144.02 ; 3204.49,1144.02 3204.49,1122.01 3155.45,1072.97 3155.45,869.64 3172.39,852.7 3172.39,804.93
RGMII_RXD1: M1.50 RN7.6 | length 2669.9
  Top Layer w6: M1.50@1985.49,926.63 cw(c1967.09,908.23) 1993.11,908.23 cw(c2019.13,908.23) M1.50@2000.73,926.63 ; M1.50@1993.11,950 1993.11,907.57 2096.29,804.39 3010.65,804.39 ; 2992.08,804.72 3032.97,804.72 3072.73,764.96 3150.39,764.96 ; v1@3154.49,774.9 cw(c3140.5,774.85) 3150.39,764.96 ; v1@3160.33,769.06 ccw(c3160.29,755.06) 3150.39,764.96 ; v1(3160.35,774.91) 3150.39,764.96 ; v1(3211.56,1736.08) 3315.68,1736.08 3356.02,1776.42 RN7.6@3398.17,1776.42 ; v1@3215.7,1731.94 cw(c3225.7,1721.94) 3225.7,1736.08 cw(c3225.7,1750.23) v1@3215.7,1740.23 ; RN7.6@3392.08,1774.36 ccw(c3387.12,1769.4) 3387.12,1776.42 ccw(c3387.12,1783.43) RN7.6@3392.08,1778.47
  Bottom Layer w6: v1@3156.21,779.06 ccw(c3146.21,789.06) 3160.35,789.06 ccw(c3174.49,789.06) v1@3164.49,779.06 ; v1@3159.89,774.46 v1(3160.35,774.91) 3160.35,846.98 3143.45,863.88 3143.45,1077.94 3192.32,1126.81 3192.32,1187.35 3167.81,1211.86 3167.81,1721.43 3182.47,1736.08 v1(3211.56,1736.08) ; v1@3207.42,1731.94 ccw(c3197.42,1721.94) 3197.42,1736.08 ccw(c3197.42,1750.23) v1@3207.42,1740.23
RGMII_RXD2: M1.57 RN7.7 | length 2057.3
  Top Layer w6: M1.57@2262.26,925.61 cw(c2252.7,912.78) 2268.7,912.78 ; M1.57@2268.7,950 2268.7,912.78 ; M1.57@2275.14,925.61 ccw(c2284.7,912.78) 2268.7,912.78 ; v1@3169.86,1130.79 ccw(c3159.86,1120.79) 3159.86,1134.93 ccw(c3159.86,1149.08) v1@3169.86,1139.08 ; v1(3174,1134.93) 3153.02,1134.93 3116.49,1098.4 3053.37,1098.4 2845.06,890.09 2291.39,890.09 2268.7,912.78 ; v1(3192.32,1754.53) 3192.43,1754.41 3312.94,1754.41 3354.63,1796.1 RN7.7@3398.17,1796.1 ; v1@3196.46,1750.38 cw(c3206.18,1740.66) 3206.18,1754.41 ; v1@3196.46,1758.67 ccw(c3206.74,1768.95) 3206.74,1754.41 ; RN7.7@3392.08,1794.05 ccw(c3387.12,1789.09) 3387.12,1796.1 ccw(c3387.12,1803.12) RN7.7@3392.08,1798.16
  Bottom Layer w6: v1@3169.86,1139.08 ccw(c3159.86,1149.08) 3174,1149.08 ccw(c3188.14,1149.08) v1@3178.14,1139.08 ; v1(3174,1134.93) 3174,1188.7 3155.81,1206.89 3155.81,1733.14 3177.2,1754.53 v1(3192.32,1754.53) ; v1@3188.18,1750.38 ccw(c3178.18,1740.38) 3178.18,1754.53 ccw(c3178.18,1768.67) v1@3188.18,1758.67
RGMII_RXD3: M1.54 RN7.8 | length 2417.4
  Top Layer w6: M1.54@2142.97,926.63 cw(c2124.57,908.23) 2150.59,908.23 cw(c2176.61,908.23) M1.54@2158.21,926.63 ; M1.54@2150.59,950 2150.59,905.37 2202.5,853.46 3052.82,853.46 3071.34,834.94 v1(3141.12,834.94) ; v1@3136.97,830.8 ccw(c3126.97,820.8) 3126.97,834.94 ccw(c3126.97,849.09) v1@3136.97,839.09 ; v1(3214.66,1774.11) 3312.94,1774.11 3354.61,1815.79 RN7.8@3398.17,1815.79 ; v1@3218.8,1769.97 cw(c3228.8,1759.97) 3228.8,1774.11 cw(c3228.8,1788.26) v1@3218.8,1778.26 ; RN7.8@3392.08,1813.73 ccw(c3387.12,1808.77) 3387.12,1815.79 ccw(c3387.12,1822.8) RN7.8@3392.08,1817.84
  Bottom Layer w6: v1@3135.26,835.09 ccw(c3122.23,835.4) 3131.45,844.61 ccw(c3140.66,853.83) v1@3140.97,840.8 ; v1(3141.12,834.94) 3131.45,844.61 3131.45,1091.35 3154.98,1114.88 3154.98,1145.92 3160.82,1151.76 3160.82,1184.91 3143.81,1201.92 3143.81,1739.01 3178.92,1774.11 v1(3214.66,1774.11) ; v1@3210.51,1769.97 ccw(c3200.51,1759.97) 3200.51,1774.11 ccw(c3200.51,1788.26) v1@3210.51,1778.26
RGMII_TXCK: M1.52 R73.2 | length 3100.1
  Top Layer w6: M1.52@2064.5,926.37 cw(c2048.7,909.45) 2071.85,909.45 ; M1.52@2071.85,950 2071.85,909.45 ; M1.52@2079.21,926.37 ccw(c2095,909.45) 2071.85,909.45 ; v1@3122.54,795.66 ccw(c3108.4,795.66) 3118.4,805.66 ccw(c3128.4,815.66) v1@3128.4,801.51 ; v1(3128.4,795.66) 3113.11,810.94 3060.86,810.94 3042.77,829.04 2152.26,829.04 2071.85,909.45 ; v1(3174.34,2043.3) 3231.39,2100.35 3510.4,2100.35 3540,2070.75 R73.2@3540,1960.94 ; v1@3174.34,2049.16 ccw(c3174.34,2063.3) 3184.34,2053.3 ccw(c3194.34,2043.3) v1@3180.19,2043.3 ; R73.2@3533.77,1967.18 ccw(c3518.73,1982.22) 3540,1982.22 ccw(c3561.27,1982.22) R73.2@3546.23,1967.18
  Bottom Layer w6: v1@3122.56,796.13 ccw(c3111.84,797) 3119.45,804.61 ccw(c3127.05,812.22) v1@3127.93,801.49 ; v1(3128.4,795.66) 3119.45,804.61 3119.45,1096.32 3142.94,1119.81 3142.94,1150.86 3148.45,1156.36 3148.45,1180.31 3131.81,1196.95 3131.81,2000.77 v1(3174.34,2043.3) ; v1@3168.48,2043.3 cw(c3154.33,2043.3) 3164.33,2033.3 cw(c3174.34,2023.3) v1@3174.34,2037.44
RGMII_TXCTL: M1.46 R74.2 | length 3033.2
  Top Layer w6: M1.46@1828.01,973.37 ccw(c1809.61,991.77) 1835.63,991.77 ccw(c1861.65,991.77) M1.46@1843.25,973.37 ; M1.46@1835.63,950 1835.63,994.62 1860.74,1019.74 2905.87,1019.74 3044.79,1158.66 3119.36,1158.66 ; v1@3123.23,1168.28 cw(c3109.99,1168.02) 3119.36,1158.66 ; v1@3128.98,1162.53 ccw(c3128.72,1149.3) 3119.36,1158.66 ; v1(3129.09,1168.39) 3119.36,1158.66 ; v1(3172.62,2071.36) 3185.33,2071.36 ; v1@3177.07,2067.55 cw(c3185.33,2060.5) 3185.33,2071.36 ; v1@3177.07,2075.17 ccw(c3185.33,2082.23) 3185.33,2071.36 ; R74.2@3571.19,1960.94 ccw(c3549.92,1960.94) 3564.96,1975.99 ccw(c3580,1991.03) R74.2@3580,1969.76 ; R74.2@3580,1960.94 3552,1988.94 3552,2075.82 3515.35,2112.47 3226.44,2112.47 3185.33,2071.36
  Bottom Layer w6: 3119.78,2004.09 3119.78,2018.53 v1(3172.62,2071.36) ; 3119.81,2004.09 3119.81,1177.67 ; v1@3123.24,1168.71 ccw(c3111.49,1169.35) 3119.81,1177.67 ; v1@3128.77,1174.24 cw(c3128.13,1185.99) 3119.81,1177.67 ; v1(3129.09,1168.39) 3119.81,1177.67 ; v1@3166.76,2071.36 cw(c3152.62,2071.36) 3162.62,2061.36 cw(c3172.62,2051.36) v1@3172.62,2065.5
RGMII_TXD0: M1.48 RN1.5 | length 3057.3
  Top Layer w6: M1.48@1908,974.45 ccw(c1898.82,986.99) 1914.37,986.99 ; M1.48@1914.37,950 1914.37,987 ; M1.48@1920.74,974.45 cw(c1929.92,986.99) 1914.37,986.99 ; 3084.82,1134.66 cw(c3084.82,1094.11) v1@3113.49,1122.78 ; 3099.3,1134.66 cw(c3099.3,1108.59) v1@3117.73,1127.02 ; v1@3111.89,1128.08 ccw(c3104.75,1129.51) 3109.9,1134.66 ; v1@3116.48,1132.67 cw(c3115.05,1139.81) 3109.9,1134.66 ; v1(3117.63,1126.92) 3109.9,1134.66 ; v1(3180.05,2096.67) 3193.67,2096.67 ; v1@3184.31,2092.64 cw(c3193.67,2083.78) 3193.67,2096.67 ; v1@3184.31,2100.69 ccw(c3193.67,2109.55) 3193.67,2096.67 ; RN1.5@3623.89,1961.01 ccw(c3618.93,1965.97) 3625.94,1965.97 ccw(c3632.96,1965.97) RN1.5@3628,1961.01 ; RN1.5@3625.94,1954.92 3625.94,2019.86 3521.18,2124.62 3221.62,2124.62 3193.67,2096.67 ; 1914.37,987 1923.11,995.74 2916,995.74 3054.92,1134.66 3109.9,1134.66
  Bottom Layer w6: v1@3113.49,1131.07 ccw(c3103.49,1141.07) 3117.63,1141.07 ccw(c3131.78,1141.07) v1@3121.78,1131.07 ; v1(3117.63,1126.92) 3117.63,1152.24 3107.78,1162.09 3107.78,2022.88 3107.76,2042.93 3161.5,2096.67 v1(3180.05,2096.67) ; v1@3175.91,2092.52 ccw(c3165.91,2082.52) 3165.91,2096.67 ccw(c3165.91,2110.81) v1@3175.91,2100.81
RGMII_TXD1: M1.49 RN1.6 | length 3418.4
  Top Layer w6: M1.49@1946.69,926.1 cw(c1933.35,910.67) 1953.74,910.67 ; M1.49@1953.74,950 1953.74,910.67 ; M1.49@1960.79,926.1 ccw(c1974.13,910.67) 1953.74,910.67 ; v1@3112.81,743.95 ccw(c3100.94,744.56) 3109.34,752.96 ; v1@3118.35,749.49 cw(c3117.74,761.36) 3109.34,752.96 ; v1(3118.66,743.64) 3109.34,752.96 ; v1(3191.63,2119.93) 3208.59,2136.89 3526.1,2136.89 3645.63,2017.36 RN1.6@3645.63,1954.92 ; v1@3191.63,2125.79 ccw(c3191.63,2139.93) 3201.63,2129.93 ccw(c3211.63,2119.93) v1@3197.49,2119.93 ; RN1.6@3643.57,1961.01 ccw(c3638.61,1965.97) 3645.63,1965.97 ccw(c3652.64,1965.97) RN1.6@3647.68,1961.01 ; 1953.74,910.67 2072.11,792.3 3028.32,792.3 3067.66,752.96 3109.34,752.96
  Bottom Layer w6: v1@3112.8,743.64 ccw(c3098.65,743.64) 3108.66,753.64 ccw(c3118.66,763.64) v1@3118.66,749.5 ; v1(3118.66,743.64) 3107.44,754.86 3107.44,1105.16 3095.76,1116.84 3095.76,2047.9 3167.79,2119.93 v1(3191.63,2119.93) ; v1@3187.49,2115.79 ccw(c3177.49,2105.79) 3177.49,2119.93 ccw(c3177.49,2134.07) v1@3187.49,2124.07
RGMII_TXD2: M1.42 RN1.7 | length 3263.4
  Top Layer w6: M1.42@1670.53,973.37 ccw(c1652.13,991.77) 1678.15,991.77 ccw(c1704.17,991.77) M1.42@1685.77,973.37 ; M1.42@1675.16,976.11 ccw(c1674.02,980.08) 1678.15,980.08 ; M1.42@1681.14,976.11 cw(c1682.28,980.08) 1678.15,980.08 ; v1@3068.02,1218.1 cw(c3053.88,1218.1) 3063.88,1208.1 cw(c3073.88,1198.1) v1@3073.88,1212.25 ; v1(3073.88,1218.1) 3062.43,1206.66 3024.52,1206.66 2885.68,1067.82 1706.99,1067.82 1678.15,1038.98 1678.15,980.08 ; v1(3173.42,2138.83) 3193.56,2138.83 3203.64,2148.91 3531.15,2148.91 3665.32,2014.74 RN1.7@3665.32,1954.92 ; v1@3177.56,2134.69 cw(c3187.56,2124.69) 3187.56,2138.83 cw(c3187.56,2152.97) v1@3177.56,2142.97 ; RN1.7@3663.26,1961.01 ccw(c3658.3,1965.97) 3665.32,1965.97 ccw(c3672.33,1965.97) RN1.7@3667.37,1961.01
  Bottom Layer w6: v1(3073.88,1218.1) 3083.61,1227.84 ; v1@3073.99,1223.96 ccw(c3074.24,1237.21) 3083.61,1227.84 ; v1@3079.74,1218.22 cw(c3092.98,1218.47) 3083.61,1227.84 ; v1@3169.28,2134.69 ccw(c3159.28,2124.69) 3159.28,2138.83 ccw(c3159.28,2152.97) v1@3169.28,2142.97 ; v1(3173.42,2138.83) 3155.2,2138.83 3083.61,2067.24 3083.61,1227.84
RGMII_TXD3: M1.58 RN1.8 | length 2777.8
  Top Layer w6: M1.58@2301.66,925.59 cw(c2292.23,912.86) 2308.07,912.86 ; M1.58@2308.07,950 2308.07,912.86 ; M1.58@2314.49,925.59 ccw(c2323.91,912.86) 2308.07,912.86 ; 2999.77,1061.77 2999.77,1061.86 ; v1@3069.38,1112.35 ccw(c3059.38,1102.35) 3059.38,1116.49 ccw(c3059.38,1130.63) v1@3069.38,1120.63 ; v1(3073.52,1116.49) 3053.73,1116.49 2999.77,1062.53 2999.77,1061.86 ; v1(3186.25,2161.17) 3536.19,2161.17 3685,2012.35 RN1.8@3685,1954.92 ; v1@3190.39,2157.02 cw(c3200.39,2147.02) 3200.39,2161.17 cw(c3200.39,2175.31) v1@3190.39,2165.31 ; RN1.8@3682.95,1961.01 ccw(c3677.99,1965.97) 3685,1965.97 ccw(c3692.01,1965.97) RN1.8@3687.05,1961.01 ; 2308.07,912.86 2318.64,902.28 2840.19,902.28 2999.77,1061.86
  Bottom Layer w6: v1@3069.38,1120.63 ccw(c3059.38,1130.63) 3073.52,1130.63 ccw(c3087.67,1130.63) v1@3077.67,1120.63 ; v1(3073.52,1116.49) 3073.52,1191.77 3055.89,1209.4 3055.89,1226.58 3071.59,1242.27 3071.59,2094.84 3137.91,2161.17 v1(3186.25,2161.17) ; v1@3182.11,2157.02 ccw(c3172.11,2147.02) 3172.11,2161.17 ccw(c3172.11,2175.31) v1@3182.11,2165.31
RPI_SCL: J1.37 M1.35 R64.1 | length 3069.8
  Top Layer w6: M1.35@1394.94,926.63 cw(c1376.53,908.23) 1402.56,908.23 cw(c1428.58,908.23) M1.35@1410.18,926.63 ; v1@1398.27,861.73 cw(c1387.92,851.38) 1402.56,851.38 ; v1@1398.27,870.02 ccw(c1387.92,880.37) 1402.56,880.37 ; 1402.56,827.02 ccw(c1437.34,827.02) R64.1@1412.75,802.43 ; 1402.56,841.51 ccw(c1451.82,841.51) R64.1@1416.99,806.67 ; 1402.56,852.08 cw(c1416.21,852.08) v1@1406.56,861.73 ; 1402.56,855.99 ccw(c1466.31,855.99) R64.1@1421.23,810.92 ; 1402.56,879.67 ccw(c1416.21,879.67) v1@1406.56,870.02 ; M1.35@1402.56,950 1402.56,817.13 ; R64.1@1406.28,805.94 ccw(c1393.25,807.82) 1402.56,817.13 ; R64.1@1413.74,813.41 cw(c1411.87,826.43) 1402.56,817.13 ; R64.1@1415,804.68 1402.56,817.13 ; J1.37@1877.87,3031.25 cw(c1872.91,3026.29) 1879.92,3026.29 cw(c1886.94,3026.29) J1.37@1881.98,3031.25 ; v1(1879.93,2864.18) 1887.6,2871.85 ; J1.37@1879.92,3051.03 1879.92,3017.46 1887.6,3009.78 1887.6,2871.85 ; v1@1881.13,2869.92 ccw(c1882.57,2876.88) 1887.6,2871.85 ; v1@1885.67,2865.37 cw(c1892.63,2866.82) 1887.6,2871.85
  Bottom Layer w6: 1392.45,875.86 ccw(c1402.41,885.83) v1@1402.41,871.73 ; 1392.4,875.91 cw(c1382.37,865.87) v1@1396.56,865.87 ; v1(1402.41,865.87) 1328.07,940.23 1328.07,2463.23 1365.87,2501.03 1542.5,2501.03 1732.15,2690.67 1851.05,2690.67 1879.93,2719.56 v1(1879.93,2864.18) ; v1@1875.79,2860.04 cw(c1865.79,2850.04) 1879.93,2850.04 cw(c1894.08,2850.04) v1@1884.08,2860.04
RPI_SDA: J1.38 M1.36 R63.1 | length 3049.2
  Top Layer w6: M1.36@1434.31,926.63 cw(c1415.9,908.23) 1441.93,908.23 cw(c1467.95,908.23) M1.36@1449.55,926.63 ; v1@1437.79,863.68 cw(c1427.79,853.68) 1441.93,853.68 cw(c1456.07,853.68) v1@1446.07,863.68 ; v1@1437.79,871.96 ccw(c1427.79,881.96) 1441.93,881.96 ccw(c1456.08,881.96) v1@1446.08,871.96 ; M1.36@1441.93,950 1441.93,822.76 R63.1@1460,804.68 ; R63.1@1451.19,804.68 ccw(c1429.92,804.68) 1444.96,819.73 ccw(c1460,834.77) R63.1@1460,813.5 ; v1@1856.07,2852.09 ccw(c1846.01,2862.15) 1860.23,2862.15 ; J1.38@1858.18,3031.25 cw(c1853.22,3026.29) 1860.23,3026.29 cw(c1867.25,3026.29) J1.38@1862.29,3031.25 ; v1@1860.23,2847.98 1860.23,2873.22 1875.6,2888.59 1875.6,3001.78 1860.23,3017.15 J1.38@1860.23,3051.03 ; 1860.23,2862.04 ccw(c1874.29,2862.04) v1@1864.35,2852.09
  Bottom Layer w6: v1@1436.07,867.82 cw(c1421.93,867.82) 1431.93,857.82 cw(c1441.93,847.82) v1@1441.93,861.96 ; v1(1441.93,867.82) 1421.54,847.43 1392.33,847.43 1379.28,860.49 1379.28,872.06 1315.93,935.4 1315.93,2468.05 1361.5,2513.62 1537.92,2513.62 1726.97,2702.67 1838.31,2702.67 1860.21,2724.57 v1(1860.21,2847.95) ; v1@1856.07,2843.81 cw(c1846.07,2833.81) 1860.21,2833.81 cw(c1874.35,2833.81) v1@1864.35,2843.81
RSET: R86.1 U9.39 | length 226
  Top Layer w8: U9.39@3715.1,1566.55 3715.1,1543.99 3745.01,1514.09 3843.15,1514.09 R86.1@3850.32,1521.26 ; 3814.15,1514.09 ccw(c3814.15,1557.42) R86.1@3844.79,1526.78 ; 3833.47,1514.09 ccw(c3833.47,1538.11) R86.1@3850.45,1521.13
RXC/PHYAD1: R71.1 R99.1 R105.2 U9.27 | length 912.5
  Top Layer w6: R105.2@3250,1960.94 3271.13,1982.07 v1(3271.13,1996.56) 3271.13,2015.45 R99.1@3250,2036.57 ; R105.2@3250,1969.76 ccw(c3250,1991.03) 3265.04,1975.99 ccw(c3280.08,1960.94) R105.2@3258.81,1960.94 ; R99.1@3250,2027.76 cw(c3250,2006.49) 3265.04,2021.53 cw(c3280.08,2036.57) R99.1@3258.81,2036.57 ; v1@3266.98,1992.42 cw(c3256.98,1982.42) 3271.13,1982.42 cw(c3285.27,1982.42) v1@3275.27,1992.42 ; v1@3266.98,2000.7 ccw(c3256.98,2010.7) 3271.13,2010.7 ccw(c3285.27,2010.7) v1@3275.27,2000.7 ; v1(3360.93,1700.8) 3367.92,1693.82 ; v1@3362.58,1695.18 cw(c3364.1,1689.99) 3367.92,1693.82 ; v1@3366.55,1699.16 ccw(c3371.74,1697.64) 3367.92,1693.82 ; R71.1@3425.87,1671.26 ccw(c3404.6,1671.26) 3419.64,1686.3 ccw(c3434.68,1701.34) R71.1@3434.68,1680.07 ; R71.1@3440.92,1665.03 cw(c3455.96,1649.99) 3455.96,1671.26 cw(c3455.96,1692.53) R71.1@3440.92,1677.49 ; U9.27@3561.6,1647.66 3511.74,1647.66 3488.14,1671.26 R71.1@3434.68,1671.26 3412.13,1693.82 3367.92,1693.82
  Bottom Layer w6: v1@3271.13,1990.7 cw(c3271.13,1976.56) 3281.13,1986.56 cw(c3291.13,1996.56) v1@3276.99,1996.56 ; v1(3271.13,1996.56) 3300.74,1966.95 3329.11,1966.95 3361.05,1935 3361.05,1763.93 3345.35,1748.22 3345.35,1716.38 v1(3360.93,1700.8) ; v1@3355.07,1700.8 ccw(c3340.93,1700.8) 3350.93,1710.8 ccw(c3360.93,1720.8) v1@3360.93,1706.66
RXCTL/PHYAD2: R72.1 R98.1 R104.2 U9.26 | length 1012.6
  Top Layer w6: R98.1@3284.6,2029.61 cw(c3257.68,1994.92) v1@3301.6,1994.92 ; R104.2@3285.54,1968.55 ccw(c3269.12,1996.56) v1(3301.6,1996.56) ; R98.1@3288.28,2034.35 cw(c3267.19,2007.17) 3301.6,2007.17 ; R104.2@3288.58,1963.37 ccw(c3275.26,1986.09) 3301.6,1986.09 ; R104.2@3290,1960.94 3301.6,1972.54 v1(3301.6,1996.56) ; R98.1@3290,2036.57 3301.6,2024.98 v1(3301.6,1996.56) ; R104.2@3291.61,1958.19 ccw(c3281.4,1975.62) 3301.6,1975.62 ; R98.1@3291.95,2039.09 cw(c3276.69,2019.41) 3301.6,2019.41 ; v1@3296.52,1993.63 cw(c3284.27,1986.56) 3297.94,1982.9 cw(c3311.6,1979.24) v1@3304.53,1991.49 ; v1@3296.52,1999.49 ccw(c3285.53,2005.84) 3297.79,2009.12 ; 3297.26,2011.11 ccw(c3312.32,2015.14) v1@3304.53,2001.64 ; v1@3297.45,1992.42 cw(c3287.45,1982.42) 3301.6,1982.42 cw(c3315.74,1982.42) v1@3305.74,1992.42 ; v1@3297.45,2000.7 ccw(c3287.45,2010.7) 3301.6,2010.7 ccw(c3315.74,2010.7) v1@3305.74,2000.7 ; v1(3363.91,1737.57) 3412.11,1737.57 R72.1@3434.68,1715 3461.37,1715 3513.01,1663.36 U9.26@3561.6,1663.36 ; v1@3368.05,1733.43 cw(c3378.05,1723.43) 3378.05,1737.57 cw(c3378.05,1751.71) v1@3368.05,1741.71 ; R72.1@3425.87,1715 ccw(c3404.6,1715) 3419.64,1730.04 ccw(c3434.68,1745.08) R72.1@3434.68,1723.81 ; R72.1@3440.92,1708.77 cw(c3455.96,1693.73) 3455.96,1715 cw(c3455.96,1736.27) R72.1@3440.92,1721.23
  Bottom Layer w6: v1@3301.6,1990.7 cw(c3301.6,1976.56) 3311.6,1986.56 cw(c3321.6,1996.56) v1@3307.45,1996.56 ; v1(3301.6,1996.56) 3319.21,1978.95 3334.08,1978.95 3373.26,1939.77 3373.26,1839.92 ; v1(3363.91,1737.57) 3373.59,1747.25 ; v1@3364.05,1743.43 ccw(c3364.35,1756.49) 3373.59,1747.25 ; v1@3369.77,1737.71 cw(c3382.83,1738.01) 3373.59,1747.25 ; 3373.59,1839.92 3373.59,1747.25
RXD0/RXDLY: R81.1 R90.2 RN7.4 U9.25 | length 757.7
  Top Layer w6: R90.2@3323.77,1967.18 ccw(c3308.73,1982.22) 3330,1982.22 ccw(c3351.27,1982.22) R90.2@3336.23,1967.18 ; R81.1@3323.77,2030.34 cw(c3308.73,2015.3) 3330,2015.3 cw(c3351.27,2015.3) R81.1@3336.23,2030.34 ; v1@3325.86,1995.86 cw(c3315.86,1985.86) 3330,1985.86 cw(c3344.14,1985.86) v1@3334.14,1995.86 ; v1@3325.86,2004.14 ccw(c3315.86,2014.14) 3330,2014.14 ccw(c3344.14,2014.14) v1@3334.14,2004.14 ; R90.2@3330,1960.94 v1(3330,2000) R81.1@3330,2036.57 ; RN7.4@3431.83,1756.73 v1(3458.23,1756.73) 3535.8,1679.16 U9.25@3561.6,1679.16 ; RN7.4@3437.92,1754.68 cw(c3442.88,1749.72) 3442.88,1756.73 cw(c3442.88,1763.75) RN7.4@3437.92,1758.79 ; v1@3454.09,1752.59 ccw(c3444.09,1742.59) 3444.09,1756.73 ccw(c3444.09,1770.88) v1@3454.09,1760.88 ; v1@3458.23,1750.87 cw(c3458.23,1736.73) 3468.23,1746.73 cw(c3478.23,1756.73) v1@3464.09,1756.73
  Bottom Layer w6: v1@3330,1994.14 cw(c3330,1980) 3340,1990 cw(c3350,2000) v1@3335.86,2000 ; v1(3330,2000) 3385.59,1944.41 3385.59,1807.75 3436.61,1756.73 v1(3458.23,1756.73) ; v1@3454.09,1752.59 ccw(c3444.09,1742.59) 3444.09,1756.73 ccw(c3444.09,1770.88) v1@3454.09,1760.88
RXD1/TXDLY: R82.1 R91.2 RN7.3 U9.24 | length 738.9
  Top Layer w6: R91.2@3363.77,1967.18 ccw(c3348.73,1982.22) 3370,1982.22 ccw(c3391.27,1982.22) R91.2@3376.23,1967.18 ; R82.1@3363.77,2030.34 cw(c3348.73,2015.3) 3370,2015.3 cw(c3391.27,2015.3) R82.1@3376.23,2030.34 ; v1@3365.86,1995.86 cw(c3355.86,1985.86) 3370,1985.86 cw(c3384.14,1985.86) v1@3374.14,1995.86 ; v1@3365.86,2004.14 ccw(c3355.86,2014.14) 3370,2014.14 ccw(c3384.14,2014.14) v1@3374.14,2004.14 ; R91.2@3370,1960.94 v1(3370,2000) R82.1@3370,2036.57 ; RN7.3@3431.83,1776.42 v1(3473.76,1776.42) 3504.05,1746.12 3504.05,1728.08 3537.27,1694.86 U9.24@3557.21,1694.86 ; RN7.3@3437.92,1774.36 cw(c3442.88,1769.4) 3442.88,1776.42 cw(c3442.88,1783.43) RN7.3@3437.92,1778.47 ; v1@3469.62,1772.28 ccw(c3459.62,1762.27) 3459.62,1776.42 ccw(c3459.62,1790.56) v1@3469.62,1780.56 ; v1@3473.76,1770.56 cw(c3473.76,1756.42) 3483.76,1766.42 cw(c3493.76,1776.42) v1@3479.62,1776.42
  Bottom Layer w6: v1@3370,1994.14 cw(c3370,1980) 3380,1990 cw(c3390,2000) v1@3375.86,2000 ; v1(3370,2000) 3398,1972 3398,1825.06 3446.64,1776.42 v1(3473.76,1776.42) ; v1@3469.62,1772.28 ccw(c3459.62,1762.27) 3459.62,1776.42 ccw(c3459.62,1790.56) v1@3469.62,1780.56
RXD2/PLLOFF: R83.1 R92.2 RN7.2 U9.23 | length 734.6
  Top Layer w6: R92.2@3403.77,1967.18 ccw(c3388.73,1982.22) 3410,1982.22 ccw(c3431.27,1982.22) R92.2@3416.23,1967.18 ; R83.1@3403.77,2030.34 cw(c3388.73,2015.3) 3410,2015.3 cw(c3431.27,2015.3) R83.1@3416.23,2030.34 ; v1@3405.86,1995.86 cw(c3395.86,1985.86) 3410,1985.86 cw(c3424.14,1985.86) v1@3414.14,1995.86 ; v1@3405.86,2004.14 ccw(c3395.86,2014.14) 3410,2014.14 ccw(c3424.14,2014.14) v1@3414.14,2004.14 ; R92.2@3410,1960.94 v1(3410,2000) R83.1@3410,2036.57 ; RN7.2@3431.83,1796.1 v1(3488.4,1796.1) 3516.05,1768.45 3516.05,1733.87 3539.26,1710.66 U9.23@3561.6,1710.66 ; RN7.2@3437.92,1794.05 cw(c3442.88,1789.09) 3442.88,1796.1 cw(c3442.88,1803.12) RN7.2@3437.92,1798.16 ; v1@3484.26,1791.96 ccw(c3474.26,1781.96) 3474.26,1796.1 ccw(c3474.26,1810.25) v1@3484.26,1800.25 ; v1@3488.4,1790.25 cw(c3488.4,1776.1) 3498.4,1786.1 cw(c3508.4,1796.1) v1@3494.26,1796.1
  Bottom Layer w6: v1@3405.86,1995.86 cw(c3395.86,1985.86) 3410,1985.86 cw(c3424.14,1985.86) v1@3414.14,1995.86 ; v1(3410,2000) 3410,1830.03 3443.93,1796.1 v1(3488.4,1796.1) ; v1@3484.26,1791.96 ccw(c3474.26,1781.96) 3474.26,1796.1 ccw(c3474.26,1810.25) v1@3484.26,1800.25
RXD3/PHYAD0: R100.1 R106.2 RN7.1 U9.22 | length 708.2
  Top Layer w6: RN7.1@3431.83,1815.79 v1(3463,1815.79) 3502.76,1815.79 3528.05,1790.5 3528.05,1740.95 3542.65,1726.36 U9.22@3561.6,1726.36 ; RN7.1@3437.92,1813.73 cw(c3442.88,1808.77) 3442.88,1815.79 cw(c3442.88,1822.8) RN7.1@3437.92,1817.84 ; R106.2@3443.77,1967.18 ccw(c3428.73,1982.22) 3450,1982.22 ccw(c3471.27,1982.22) R106.2@3456.23,1967.18 ; R100.1@3443.77,2030.34 cw(c3428.73,2015.3) 3450,2015.3 cw(c3471.27,2015.3) R100.1@3456.23,2030.34 ; v1@3445.86,1995.86 cw(c3435.86,1985.86) 3450,1985.86 cw(c3464.14,1985.86) v1@3454.14,1995.86 ; v1@3445.86,2004.14 ccw(c3435.86,2014.14) 3450,2014.14 ccw(c3464.14,2014.14) v1@3454.14,2004.14 ; R106.2@3450,1960.94 v1(3450,2000) R100.1@3450,2036.57 ; v1@3458.86,1811.65 ccw(c3448.86,1801.65) 3448.86,1815.79 ccw(c3448.86,1829.93) v1@3458.86,1819.93 ; v1@3467.14,1811.65 cw(c3477.14,1801.65) 3477.14,1815.79 cw(c3477.14,1829.93) v1@3467.14,1819.93
  Bottom Layer w6: v1@3444.14,2000 cw(c3430,2000) 3440,1990 cw(c3450,1980) v1@3450,1994.14 ; v1(3450,2000) 3422,1972 3422,1835 3441.21,1815.79 v1(3463,1815.79) ; v1@3458.86,1811.65 ccw(c3448.86,1801.65) 3448.86,1815.79 ccw(c3448.86,1829.93) v1@3458.86,1819.93
SD_CLK: M1.30 R26.2 | length 739.4
  Top Layer w6: R26.2@855.04,900.28 872.98,918.22 953.58,918.22 994.06,958.7 1103.04,958.7 1142.83,998.49 1142.83,1219.81 1195.86,1272.83 ; R26.2@855.04,909.09 ccw(c855.04,930.36) 870.08,915.32 ccw(c885.12,900.28) R26.2@863.85,900.28 ; M1.30@1213.74,1265.3 ccw(c1195.86,1247.84) 1195.86,1272.83 ; M1.30@1213.74,1280.37 cw(c1195.86,1297.83) 1195.86,1272.83 ; M1.30@1237.2,1272.83 1195.86,1272.83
